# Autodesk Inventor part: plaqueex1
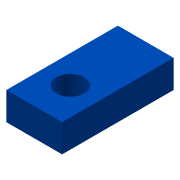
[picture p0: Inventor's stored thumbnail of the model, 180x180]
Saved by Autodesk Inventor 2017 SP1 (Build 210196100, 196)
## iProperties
Created: 2006-05
Part Number: plaqueex1
Document SubType Name: Modeling
Designer: Administrateur
Manufacturer: Standard
Standards Organization: Custom
Material: Acier
Mass: 56.6346 g
Surface Area: 29.5708 cm^2
Volume: 7.2146 cm^3
Density: 7.85 g/cm^3
Appearance: Cyan
Author: Administrateur
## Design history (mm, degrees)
sketch "Esquisse1"
  geometry: L1 (-17.615, 18.022)-(2.385, 18.022); L2 (2.385, 18.022)-(2.385, -21.978); L3 (2.385, -21.978)-(-17.615, -21.978); L4 (-17.615, -21.978)-(-17.615, 18.022); C1 r 5 at (-7.615, -9.079)
  constraints: 8 end point, 2 parallel, 1 centre point, 1 horizontal, 1 perpendicular
  dimensions: "d0" = 20 distance of L1.start L1.end; "d1" = 40 distance of L3.end L1.start; "d2" = 10 diameter of C1; "d5" = 10 distance from line of L4 C1.centre (= 0.5 x d0)
extrude "Extrusion1" new body sketch "Esquisse1" distance "d3" = 10; taper "d4" = 0 deg
node "Solide1"
node "Corps solides"
node "Corps surfaciques"
